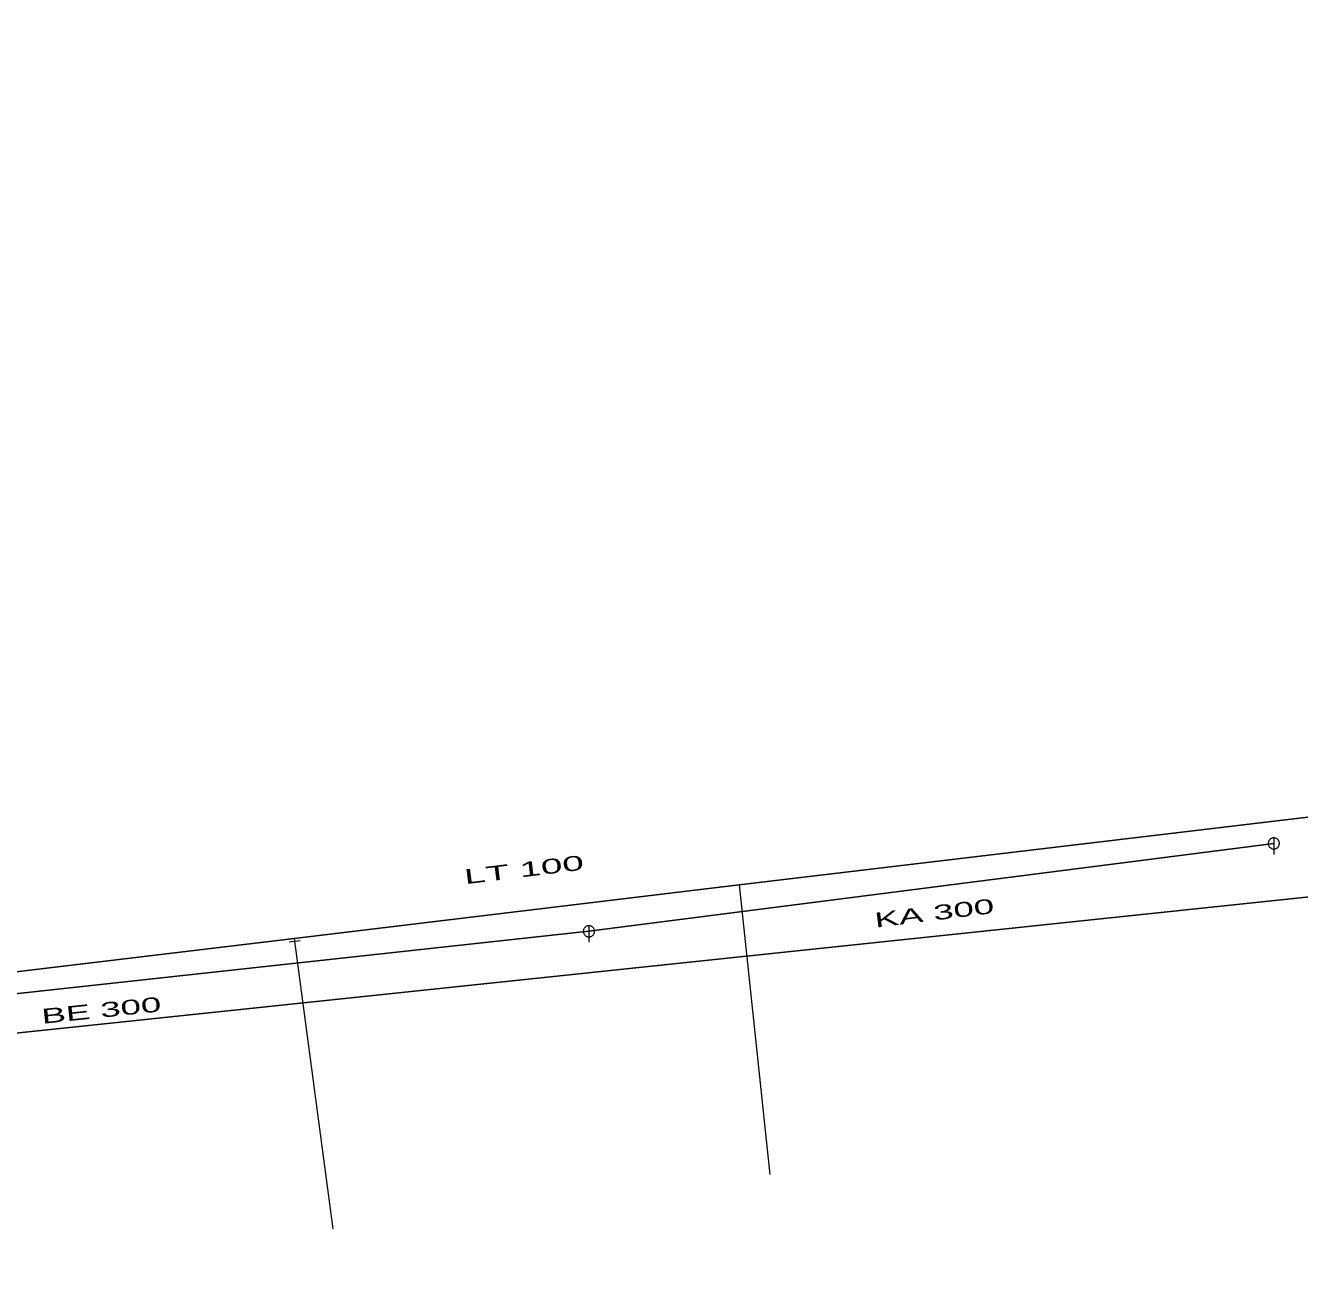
# Model space of a CAD drawing. Extents: x -687515 to -686506, y -974029 to -973461.
# Drawn here: x -686842.4 to -686785, y -973577 to -973520.6 of the extents above; entities that cross this region are included whole.
import ezdxf
from ezdxf.enums import TextEntityAlignment as Align

# ---------------------------------------------------------------- set-up
doc = ezdxf.new("R2010")
doc.units = 0
doc.header["$LTSCALE"] = 0.27
for name, color, linetype, lineweight in [('1', 7, 'Continuous', 13), ('13', 7, 'Continuous', 13), ('14', 7, 'Continuous', 25), ('17', 7, 'Continuous', 25), ('22', 7, 'Continuous', 13), ('34', 7, 'Continuous', 13)]:
    doc.layers.add(name, color=color, linetype=linetype, lineweight=lineweight)

msp = doc.modelspace()

# ---------------------------------------------------------------- linework, layer by layer
at = {"layer": '13'}
for p, q in [((-686810.25, -973559.235), (-686808.873, -973572.265)), ((-686830.257, -973561.773), (-686828.543, -973574.716))]:
    msp.add_line(p, q, dxfattribs=at)
at = {"layer": '14'}
for p, q in [((-686786.202, -973557.376), (-686817.017, -973561.325)), ((-686817.017, -973561.324), (-686861.107, -973566.122))]:
    msp.add_line(p, q, dxfattribs=at)
at = {"layer": '14', "lineweight": 13}
msp.add_line((-686830.283, -973561.643), (-686830.257, -973561.773), dxfattribs=at)
at = {"layer": '17'}
for points in [[(-686645.309, -973464.46), (-686646.34, -973464.75), (-686680.188, -973471.317), (-686771.188, -973470.317), (-686761.188, -973557.317), (-686894.188, -973571.317), (-686953.188, -973578.317), (-686955.188, -973554.317), (-687116.188, -973577.317), (-687229.188, -973601.317), (-687468.188, -973649.317), (-687458.188, -973700.317)], [(-686865.945, -973565.93), (-686830.283, -973561.643), (-686810.25, -973559.234), (-686773.456, -973554.854), (-686769.061, -973554.686)]]:
    msp.add_lwpolyline(points, dxfattribs=at)
at = {"layer": '22'}
for p, q in [((-686786.201, -973557.124), (-686786.202, -973557.868)), ((-686817.016, -973561.073), (-686817.017, -973561.816))]:
    msp.add_line(p, q, dxfattribs=at)
for points in [[(-686785.95, -973557.376), (-686785.951, -973557.35), (-686785.955, -973557.324), (-686785.961, -973557.298), (-686785.971, -973557.274), (-686785.983, -973557.25), (-686785.997, -973557.228), (-686786.014, -973557.207), (-686786.032, -973557.189), (-686786.053, -973557.172), (-686786.075, -973557.158), (-686786.099, -973557.146), (-686786.123, -973557.136), (-686786.149, -973557.13), (-686786.175, -973557.126), (-686786.201, -973557.124), (-686786.227, -973557.125), (-686786.253, -973557.129), (-686786.279, -973557.135), (-686786.304, -973557.145), (-686786.327, -973557.157), (-686786.349, -973557.171), (-686786.37, -973557.188), (-686786.388, -973557.206), (-686786.405, -973557.227), (-686786.419, -973557.249), (-686786.431, -973557.273), (-686786.441, -973557.297), (-686786.448, -973557.323), (-686786.452, -973557.349), (-686786.454, -973557.375), (-686786.453, -973557.401), (-686786.449, -973557.427), (-686786.442, -973557.453), (-686786.432, -973557.478), (-686786.42, -973557.501), (-686786.406, -973557.523), (-686786.389, -973557.544), (-686786.371, -973557.562), (-686786.35, -973557.579), (-686786.328, -973557.593), (-686786.305, -973557.605), (-686786.28, -973557.615), (-686786.254, -973557.622), (-686786.228, -973557.626), (-686786.202, -973557.628), (-686786.176, -973557.627), (-686786.15, -973557.623), (-686786.124, -973557.616), (-686786.1, -973557.606), (-686786.076, -973557.594), (-686786.054, -973557.58), (-686786.033, -973557.563), (-686786.015, -973557.545), (-686785.998, -973557.524), (-686785.984, -973557.502), (-686785.972, -973557.479), (-686785.962, -973557.454), (-686785.956, -973557.428), (-686785.952, -973557.402)], [(-686816.765, -973561.325), (-686816.766, -973561.299), (-686816.77, -973561.273), (-686816.776, -973561.247), (-686816.786, -973561.223), (-686816.798, -973561.199), (-686816.812, -973561.177), (-686816.829, -973561.156), (-686816.847, -973561.138), (-686816.868, -973561.121), (-686816.89, -973561.107), (-686816.914, -973561.095), (-686816.938, -973561.085), (-686816.964, -973561.079), (-686816.99, -973561.075), (-686817.016, -973561.073), (-686817.042, -973561.074), (-686817.068, -973561.078), (-686817.094, -973561.084), (-686817.119, -973561.094), (-686817.142, -973561.106), (-686817.164, -973561.12), (-686817.185, -973561.137), (-686817.203, -973561.155), (-686817.22, -973561.176), (-686817.234, -973561.198), (-686817.246, -973561.222), (-686817.256, -973561.246), (-686817.263, -973561.272), (-686817.267, -973561.298), (-686817.269, -973561.324), (-686817.268, -973561.35), (-686817.264, -973561.376), (-686817.257, -973561.402), (-686817.247, -973561.427), (-686817.235, -973561.45), (-686817.221, -973561.472), (-686817.204, -973561.493), (-686817.186, -973561.511), (-686817.165, -973561.528), (-686817.143, -973561.542), (-686817.12, -973561.554), (-686817.095, -973561.564), (-686817.069, -973561.571), (-686817.043, -973561.575), (-686817.017, -973561.576), (-686816.991, -973561.576), (-686816.965, -973561.572), (-686816.939, -973561.565), (-686816.915, -973561.555), (-686816.891, -973561.543), (-686816.869, -973561.529), (-686816.848, -973561.512), (-686816.83, -973561.494), (-686816.813, -973561.473), (-686816.799, -973561.451), (-686816.787, -973561.428), (-686816.777, -973561.403), (-686816.771, -973561.377), (-686816.767, -973561.351)]]:
    msp.add_lwpolyline(points, close=True, dxfattribs=at)
at = {"layer": '34'}
msp.add_line((-686830.503, -973561.802), (-686830.01, -973561.743), dxfattribs=at)

# ---------------------------------------------------------------- texts
at = {"layer": '1'}
for s, rotation, width, p in [('LT 100', 7, 1.95, (-686819.901, -973558.881)), ('KA 300', 7, 1.85, (-686801.438, -973560.834)), ('BE 300', 6, 1.85, (-686838.919, -973565.208))]:
    msp.add_text(s, height=0.6667, rotation=rotation, dxfattribs=dict(at, width=width)).set_placement(p, align=Align.CENTER)

doc.saveas('drawing.dxf')
